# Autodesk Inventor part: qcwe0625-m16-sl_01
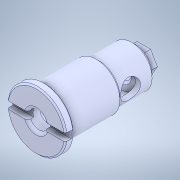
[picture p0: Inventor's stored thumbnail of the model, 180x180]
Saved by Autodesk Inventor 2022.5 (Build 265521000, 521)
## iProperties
Created: 2023-04
Part Number: qcwe0625-m16-sl_01
Material: Generic
Document SubType Name: Modeling
Designer: ImaoCorp
Density: 1 g/cm^3
Appearance: Default
Author: ImaoCorp
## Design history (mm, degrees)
feature "qcwe0625-m16-sl_01"
node "ソリッド1"
